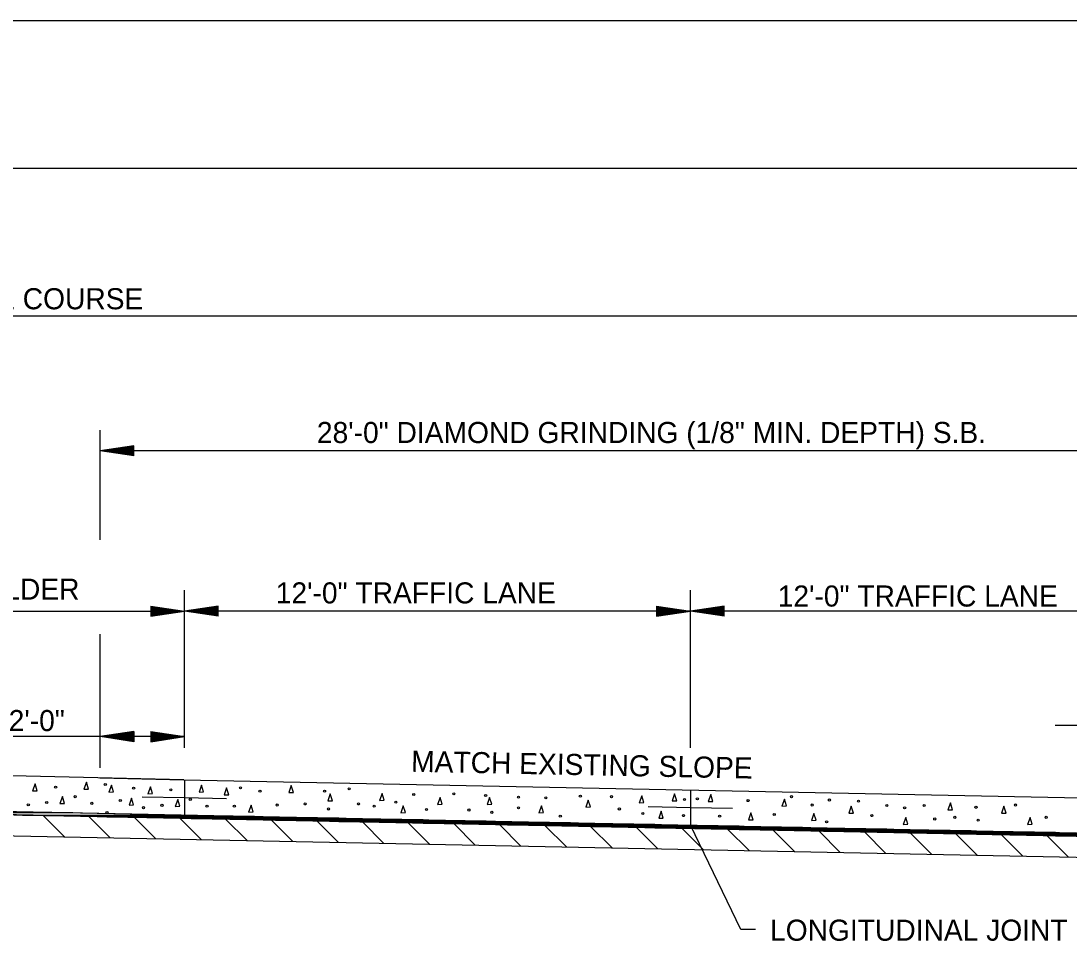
# Model space of a CAD drawing. Extents: x 60325 to 61047, y 53669 to 53767.
# Drawn here: x 60578.67 to 60603.53, y 53731.77 to 53753.59 of the extents above; entities that cross this region are included whole.
import ezdxf

# ---------------------------------------------------------------- set-up
doc = ezdxf.new("R2010")
doc.units = 0
doc.layers.add('R_Border', color=7, linetype='Continuous')
doc.layers.add('R_Border Prem', color=7, linetype='Continuous')

msp = doc.modelspace()

# ---------------------------------------------------------------- linework, layer by layer
at = {"layer": 'R_Border'}
for p, q in [((60580.545, 53741.281), (60580.545, 53743.886)), ((60581.345, 53743.516), (60580.545, 53743.396)), ((60581.345, 53743.496), (60580.679, 53743.396)), ((60581.345, 53743.476), (60580.816, 53743.396)), ((60581.345, 53743.276), (60581.345, 53743.516)), ((60608.545, 53743.396), (60580.545, 53743.396)), ((60581.345, 53743.276), (60580.545, 53743.396)), ((60581.345, 53743.296), (60580.679, 53743.396)), ((60581.345, 53743.317), (60580.816, 53743.396)), ((60581.345, 53743.456), (60580.95, 53743.396)), ((60581.345, 53743.337), (60580.95, 53743.396)), ((60581.345, 53743.435), (60581.085, 53743.396)), ((60581.345, 53743.357), (60581.085, 53743.396)), ((60581.345, 53743.415), (60581.219, 53743.396)), ((60581.345, 53743.377), (60581.219, 53743.396)), ((60582.545, 53736.351), (60582.545, 53740.091)), ((60594.545, 53736.351), (60594.545, 53740.091)), ((60572.545, 53739.591), (60582.545, 53739.591)), ((60581.745, 53739.711), (60582.545, 53739.591)), ((60581.745, 53739.711), (60581.745, 53739.471)), ((60581.745, 53739.691), (60582.412, 53739.591)), ((60581.745, 53739.671), (60582.274, 53739.591)), ((60581.745, 53739.651), (60582.141, 53739.591)), ((60581.745, 53739.63), (60582.005, 53739.591)), ((60581.745, 53739.61), (60581.872, 53739.591)), ((60581.745, 53739.471), (60582.545, 53739.591)), ((60581.745, 53739.552), (60582.005, 53739.591)), ((60581.745, 53739.512), (60582.274, 53739.591)), ((60581.745, 53739.491), (60582.412, 53739.591)), ((60581.745, 53739.532), (60582.141, 53739.591)), ((60581.745, 53739.572), (60581.872, 53739.591)), ((60583.345, 53739.711), (60582.545, 53739.591)), ((60583.345, 53739.471), (60582.545, 53739.591)), ((60594.545, 53739.591), (60582.545, 53739.591)), ((60583.345, 53739.691), (60582.679, 53739.591)), ((60583.345, 53739.491), (60582.679, 53739.591)), ((60583.345, 53739.671), (60582.816, 53739.591)), ((60583.345, 53739.512), (60582.816, 53739.591)), ((60583.345, 53739.651), (60582.95, 53739.591)), ((60583.345, 53739.532), (60582.95, 53739.591)), ((60583.345, 53739.63), (60583.085, 53739.591)), ((60583.345, 53739.552), (60583.085, 53739.591)), ((60583.345, 53739.61), (60583.219, 53739.591)), ((60583.345, 53739.572), (60583.219, 53739.591)), ((60583.345, 53739.471), (60583.345, 53739.711)), ((60593.745, 53739.711), (60594.545, 53739.591)), ((60593.745, 53739.711), (60593.745, 53739.471)), ((60593.745, 53739.691), (60594.412, 53739.591)), ((60593.745, 53739.671), (60594.274, 53739.591)), ((60593.745, 53739.651), (60594.141, 53739.591)), ((60593.745, 53739.63), (60594.005, 53739.591)), ((60593.745, 53739.61), (60593.872, 53739.591)), ((60593.745, 53739.471), (60594.545, 53739.591)), ((60593.745, 53739.552), (60594.005, 53739.591)), ((60593.745, 53739.512), (60594.274, 53739.591)), ((60593.745, 53739.491), (60594.412, 53739.591)), ((60593.745, 53739.532), (60594.141, 53739.591)), ((60593.745, 53739.572), (60593.872, 53739.591)), ((60595.345, 53739.711), (60594.545, 53739.591)), ((60606.545, 53739.591), (60594.545, 53739.591)), ((60595.345, 53739.471), (60594.545, 53739.591)), ((60595.345, 53739.691), (60594.679, 53739.591)), ((60595.345, 53739.491), (60594.679, 53739.591)), ((60595.345, 53739.671), (60594.816, 53739.591)), ((60595.345, 53739.512), (60594.816, 53739.591)), ((60595.345, 53739.651), (60594.95, 53739.591)), ((60595.345, 53739.532), (60594.95, 53739.591)), ((60595.345, 53739.63), (60595.085, 53739.591)), ((60595.345, 53739.552), (60595.085, 53739.591)), ((60595.345, 53739.61), (60595.219, 53739.591)), ((60595.345, 53739.572), (60595.219, 53739.591)), ((60595.345, 53739.471), (60595.345, 53739.711)), ((60580.545, 53735.878), (60580.545, 53739.042)), ((60603.198, 53736.885), (60606.545, 53736.885)), ((60580.545, 53736.615), (60578.151, 53736.615)), ((60581.345, 53736.735), (60580.545, 53736.615)), ((60581.345, 53736.495), (60580.545, 53736.615)), ((60582.545, 53736.615), (60580.545, 53736.615)), ((60581.345, 53736.715), (60580.679, 53736.615)), ((60581.345, 53736.515), (60580.679, 53736.615)), ((60581.345, 53736.695), (60580.816, 53736.615)), ((60581.345, 53736.536), (60580.816, 53736.615)), ((60581.345, 53736.675), (60580.95, 53736.615)), ((60581.345, 53736.556), (60580.95, 53736.615)), ((60581.345, 53736.654), (60581.085, 53736.615)), ((60581.345, 53736.576), (60581.085, 53736.615)), ((60581.345, 53736.634), (60581.219, 53736.615)), ((60581.345, 53736.596), (60581.219, 53736.615)), ((60581.345, 53736.735), (60581.345, 53736.495)), ((60581.745, 53736.735), (60582.545, 53736.615)), ((60581.745, 53736.735), (60581.745, 53736.495)), ((60581.745, 53736.715), (60582.412, 53736.615)), ((60581.745, 53736.695), (60582.274, 53736.615)), ((60581.745, 53736.675), (60582.141, 53736.615)), ((60581.745, 53736.654), (60582.005, 53736.615)), ((60581.745, 53736.634), (60581.872, 53736.615)), ((60581.745, 53736.495), (60582.545, 53736.615)), ((60581.745, 53736.576), (60582.005, 53736.615)), ((60581.745, 53736.536), (60582.274, 53736.615)), ((60581.745, 53736.515), (60582.412, 53736.615)), ((60581.745, 53736.556), (60582.141, 53736.615)), ((60581.745, 53736.596), (60581.872, 53736.615)), ((60582.543, 53735.586), (60582.543, 53734.753)), ((60594.545, 53735.351), (60594.545, 53734.518)), ((60581.543, 53735.189), (60582.543, 53735.169)), ((60582.543, 53735.169), (60583.543, 53735.149)), ((60593.545, 53734.955), (60594.545, 53734.935)), ((60594.545, 53734.935), (60595.545, 53734.915)), ((60595.746, 53732.038), (60594.545, 53734.518)), ((60596.093, 53732.038), (60595.746, 53732.038))]:
    msp.add_line(p, q, dxfattribs=at)
msp.add_lwpolyline([(60580.54, 53735.636), (60582.53, 53735.592), (60608.545, 53735.071)], dxfattribs=at)
at = {"layer": 'R_Border Prem'}
for p, q in [((60608.545, 53753.591), (60534.545, 53753.591)), ((60610.545, 53750.091), (60532.545, 53750.091)), ((60610.545, 53746.591), (60532.545, 53746.591)), ((60582.53, 53735.592), (60572.541, 53735.811)), ((60571.545, 53734.978), (60610.545, 53734.198)), ((60571.545, 53734.898), (60610.545, 53734.118)), ((60575.4, 53734.821), (60579.401, 53734.821)), ((60575.9, 53734.811), (60579.901, 53734.811)), ((60578.704, 53734.755), (60582.705, 53734.755)), ((60579.191, 53734.745), (60579.702, 53734.235)), ((60579.204, 53734.745), (60583.205, 53734.745)), ((60579.704, 53734.735), (60583.705, 53734.735)), ((60580.204, 53734.725), (60584.205, 53734.725)), ((60580.274, 53734.723), (60580.784, 53734.213)), ((60580.704, 53734.715), (60584.705, 53734.715)), ((60581.204, 53734.705), (60585.205, 53734.705)), ((60581.356, 53734.702), (60581.866, 53734.191)), ((60581.704, 53734.695), (60585.705, 53734.695)), ((60582.204, 53734.685), (60586.205, 53734.685)), ((60582.443, 53734.676), (60582.949, 53734.17)), ((60582.704, 53734.675), (60586.705, 53734.675)), ((60583.204, 53734.665), (60587.205, 53734.665)), ((60583.521, 53734.658), (60584.031, 53734.148)), ((60583.704, 53734.655), (60587.705, 53734.655)), ((60584.204, 53734.645), (60588.205, 53734.645)), ((60584.603, 53734.637), (60585.113, 53734.126)), ((60584.704, 53734.635), (60588.705, 53734.635)), ((60585.204, 53734.625), (60589.205, 53734.625)), ((60585.685, 53734.615), (60586.196, 53734.105)), ((60585.704, 53734.615), (60589.705, 53734.615)), ((60586.204, 53734.605), (60590.205, 53734.605)), ((60586.704, 53734.595), (60590.705, 53734.595)), ((60586.768, 53734.593), (60587.278, 53734.083)), ((60587.204, 53734.585), (60591.205, 53734.585)), ((60587.704, 53734.575), (60591.705, 53734.575)), ((60587.85, 53734.572), (60588.36, 53734.062)), ((60588.204, 53734.565), (60592.205, 53734.565)), ((60588.704, 53734.555), (60592.705, 53734.555)), ((60588.932, 53734.55), (60589.443, 53734.04)), ((60589.204, 53734.545), (60593.205, 53734.545)), ((60589.704, 53734.535), (60593.705, 53734.535)), ((60590.015, 53734.529), (60590.525, 53734.018)), ((60590.204, 53734.525), (60594.205, 53734.525)), ((60571.545, 53734.398), (60625.091, 53733.327)), ((60590.704, 53734.515), (60594.705, 53734.515)), ((60591.097, 53734.507), (60591.607, 53733.997)), ((60591.204, 53734.505), (60595.205, 53734.505)), ((60591.704, 53734.495), (60595.705, 53734.495)), ((60592.179, 53734.485), (60592.689, 53733.975)), ((60592.204, 53734.485), (60596.205, 53734.485)), ((60592.704, 53734.475), (60596.705, 53734.475)), ((60593.204, 53734.465), (60597.205, 53734.465)), ((60593.261, 53734.464), (60593.772, 53733.953)), ((60593.704, 53734.455), (60597.705, 53734.455)), ((60594.204, 53734.445), (60598.205, 53734.445)), ((60594.344, 53734.442), (60594.854, 53733.932)), ((60594.704, 53734.435), (60598.705, 53734.435)), ((60595.204, 53734.425), (60599.205, 53734.425)), ((60595.426, 53734.42), (60595.936, 53733.91)), ((60595.704, 53734.415), (60599.705, 53734.415)), ((60596.204, 53734.405), (60600.205, 53734.405)), ((60596.508, 53734.399), (60597.019, 53733.888)), ((60596.704, 53734.395), (60600.705, 53734.395)), ((60597.204, 53734.385), (60601.205, 53734.385)), ((60597.591, 53734.377), (60598.101, 53733.867)), ((60597.704, 53734.375), (60601.705, 53734.375)), ((60598.204, 53734.365), (60602.205, 53734.365)), ((60598.673, 53734.355), (60599.183, 53733.845)), ((60598.704, 53734.355), (60602.705, 53734.355)), ((60599.204, 53734.345), (60603.205, 53734.345)), ((60599.704, 53734.335), (60603.705, 53734.335)), ((60599.755, 53734.334), (60600.266, 53733.823)), ((60600.204, 53734.325), (60604.205, 53734.325)), ((60600.704, 53734.315), (60604.705, 53734.315)), ((60600.838, 53734.312), (60601.348, 53733.802)), ((60601.204, 53734.305), (60605.205, 53734.305)), ((60601.704, 53734.295), (60605.705, 53734.295)), ((60601.92, 53734.29), (60602.43, 53733.78)), ((60602.204, 53734.285), (60606.205, 53734.285)), ((60602.704, 53734.275), (60606.705, 53734.275)), ((60603.002, 53734.269), (60603.513, 53733.758)), ((60603.204, 53734.265), (60607.205, 53734.265))]:
    msp.add_line(p, q, dxfattribs=at)
for points in [[(60580.219, 53735.531), (60580.158, 53735.365), (60580.268, 53735.37), (60580.219, 53735.531)], [(60579.004, 53735.491), (60578.943, 53735.325), (60579.053, 53735.329), (60579.004, 53735.491)], [(60580.813, 53735.465), (60580.753, 53735.299), (60580.863, 53735.304), (60580.813, 53735.465)], [(60581.737, 53735.425), (60581.676, 53735.259), (60581.786, 53735.263), (60581.737, 53735.425)], [(60582.952, 53735.465), (60582.891, 53735.299), (60583.001, 53735.304), (60582.952, 53735.465)], [(60583.547, 53735.399), (60583.486, 53735.233), (60583.596, 53735.237), (60583.547, 53735.399)], [(60585.08, 53735.452), (60585.019, 53735.286), (60585.129, 53735.29), (60585.08, 53735.452)], [(60587.234, 53735.267), (60587.173, 53735.101), (60587.283, 53735.105), (60587.234, 53735.267)], [(60579.652, 53735.191), (60579.591, 53735.025), (60579.701, 53735.029), (60579.652, 53735.191)], [(60581.291, 53735.157), (60581.231, 53734.991), (60581.341, 53734.996), (60581.291, 53735.157)], [(60582.385, 53735.125), (60582.324, 53734.959), (60582.434, 53734.963), (60582.385, 53735.125)], [(60586.005, 53735.254), (60585.944, 53735.088), (60586.054, 53735.092), (60586.005, 53735.254)], [(60588.608, 53735.174), (60588.548, 53735.008), (60588.658, 53735.013), (60588.608, 53735.174)], [(60589.784, 53735.174), (60589.724, 53735.008), (60589.834, 53735.013), (60589.784, 53735.174)], [(60592.124, 53735.108), (60592.063, 53734.942), (60592.173, 53734.947), (60592.124, 53735.108)], [(60593.392, 53735.214), (60593.332, 53735.048), (60593.442, 53735.052), (60593.392, 53735.214)], [(60594.172, 53735.254), (60594.112, 53735.088), (60594.222, 53735.092), (60594.172, 53735.254)], [(60595.031, 53735.24), (60594.971, 53735.074), (60595.081, 53735.079), (60595.031, 53735.24)], [(60596.776, 53735.135), (60596.715, 53734.969), (60596.825, 53734.973), (60596.776, 53735.135)], [(60600.714, 53735.042), (60600.653, 53734.876), (60600.763, 53734.881), (60600.714, 53735.042)], [(60584.128, 53734.989), (60584.068, 53734.823), (60584.178, 53734.828), (60584.128, 53734.989)], [(60587.736, 53734.976), (60587.675, 53734.81), (60587.785, 53734.815), (60587.736, 53734.976)], [(60591.013, 53734.976), (60590.953, 53734.81), (60591.063, 53734.815), (60591.013, 53734.976)], [(60593.855, 53734.844), (60593.794, 53734.678), (60593.904, 53734.682), (60593.855, 53734.844)], [(60595.983, 53734.804), (60595.922, 53734.638), (60596.032, 53734.643), (60595.983, 53734.804)], [(60597.476, 53734.791), (60597.416, 53734.625), (60597.526, 53734.63), (60597.476, 53734.791)], [(60598.362, 53734.963), (60598.301, 53734.797), (60598.411, 53734.801), (60598.362, 53734.963)], [(60601.983, 53734.963), (60601.922, 53734.797), (60602.032, 53734.801), (60601.983, 53734.963)], [(60599.657, 53734.699), (60599.596, 53734.533), (60599.706, 53734.537), (60599.657, 53734.699)], [(60602.604, 53734.699), (60602.543, 53734.533), (60602.653, 53734.537), (60602.604, 53734.699)]]:
    msp.add_lwpolyline(points, dxfattribs=at)
msp.add_lwpolyline([(60571.545, 53734.978), (60594.545, 53734.518), (60594.545, 53734.438), (60571.545, 53734.898)], close=True, dxfattribs=at)
for centre in [(60579.49, 53735.417), (60580.668, 53735.48), (60581.34, 53735.391), (60582.223, 53735.351), (60583.874, 53735.401), (60584.337, 53735.322), (60585.87, 53735.322), (60586.451, 53735.375), (60587.984, 53735.243), (60588.936, 53735.256), (60578.842, 53734.996), (60579.279, 53735.052), (60579.952, 53735.19), (60580.348, 53735.031), (60581.024, 53735.1), (60582.685, 53735.124), (60585.407, 53735.018), (60586.676, 53735.018), (60587.561, 53735.058), (60589.689, 53735.216), (60590.469, 53735.177), (60591.116, 53735.164), (60591.936, 53735.203), (60592.676, 53735.19), (60594.407, 53735.124), (60594.711, 53735.137), (60595.914, 53735.097), (60596.945, 53735.19), (60597.843, 53735.111), (60598.531, 53735.084), (60580.708, 53734.816), (60581.575, 53734.929), (60582.012, 53734.986), (60583.081, 53734.965), (60583.729, 53734.965), (60584.746, 53734.992), (60585.962, 53734.899), (60587.046, 53734.965), (60588.288, 53734.886), (60589.293, 53734.873), (60589.835, 53734.82), (60590.469, 53734.926), (60592.861, 53734.899), (60593.416, 53734.793), (60596.535, 53734.767), (60597.434, 53734.992), (60599.205, 53734.979), (60599.627, 53734.926), (60600.09, 53734.979), (60601.319, 53734.939), (60602.257, 53734.992), (60591.46, 53734.727), (60594.381, 53734.741), (60595.24, 53734.727), (60597.777, 53734.595), (60598.848, 53734.741), (60600.341, 53734.661), (60600.817, 53734.701), (60601.372, 53734.635), (60602.984, 53734.701)]:
    msp.add_circle(centre, 0.025, dxfattribs=at)

# ---------------------------------------------------------------- texts
at = {"layer": 'R_Border'}
for s, p in [('28\'-0" DIAMOND GRINDING (1/8" MIN. DEPTH) S.B.', (60585.687, 53743.579)), ('10\'-0" SHOULDER', (60574.452, 53739.863)), ('12\'-0" TRAFFIC LANE', (60584.712, 53739.774)), ('12\'-0" TRAFFIC LANE', (60596.617, 53739.7)), ('2\'-0"', (60578.377, 53736.746)), ('LONGITUDINAL JOINT', (60596.435, 53731.773))]:
    msp.add_text(s, height=0.5, dxfattribs=at).set_placement(p)
msp.add_text('MATCH EXISTING SLOPE', height=0.5, rotation=358.8542, dxfattribs=at).set_placement((60587.919, 53735.781))
at = {"layer": 'R_Border Prem'}
msp.add_text('EXISTING 78\'-0" CEMENT STABILIZED CRUSHED STONE BASE COURSE', height=0.5, dxfattribs=at).set_placement((60558.542, 53746.752))

doc.saveas('drawing.dxf')
